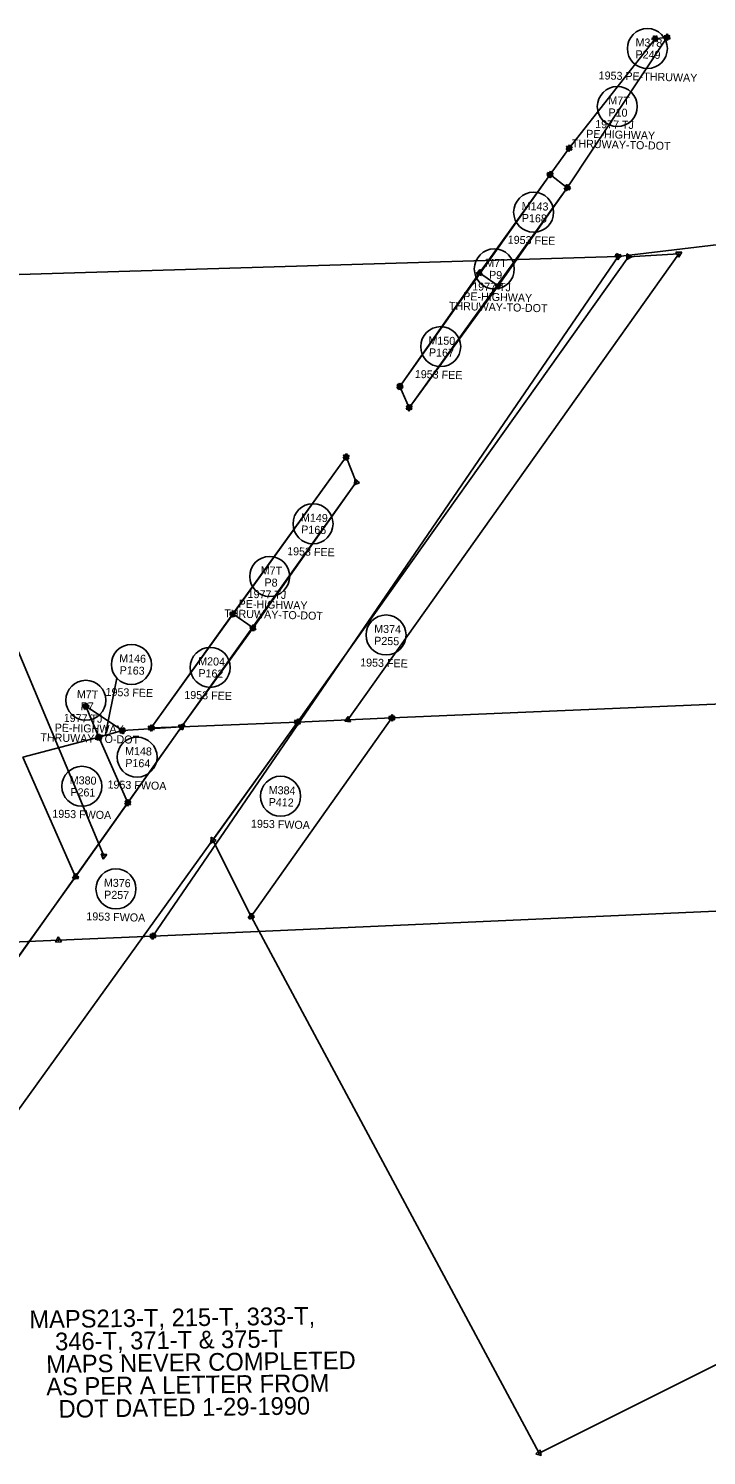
# Model space of a CAD drawing. Extents: x 325029 to 414988, y 1517527 to 1550420.
# Drawn here: x 360105 to 360549, y 1524410 to 1525346 of the extents above; entities that cross this region are included whole.
import ezdxf

# ---------------------------------------------------------------- set-up
doc = ezdxf.new("R2010")
doc.units = 0
for name, color, linetype in [('Level 56', 7, 'Continuous'), ('MEE', 7, 'Continuous'), ('MHB', 7, 'Continuous'), ('MHBWOA', 7, 'Continuous'), ('MRBL1', 7, 'Continuous'), ('MRBL2', 7, 'Continuous'), ('MRBL3', 7, 'Continuous'), ('NNSH_P_T', 7, 'Continuous'), ('S_C', 7, 'Continuous')]:
    doc.layers.add(name, color=color, linetype=linetype)

msp = doc.modelspace()

# ---------------------------------------------------------------- linework, layer by layer
at = {"layer": 'Level 56'}
for centre in [(360510.67, 1525333.37), (360490.95, 1525295.34), (360436.07, 1525226), (360410.26, 1525188.82), (360375.12, 1525137.86), (360291.35, 1525021.65), (360262.93, 1524987.07), (360339.26, 1524948.69), (360172.22, 1524929.34), (360223.9, 1524927.42), (360142.33, 1524905.83), (360175.95, 1524868.55), (360139.74, 1524849.41), (360270.07, 1524842.89), (360162.08, 1524782.11)]:
    msp.add_circle(centre, 13.12, dxfattribs=at)
at = {"layer": 'MEE'}
for p, q in [((360523.65, 1525340.76), (360458.11, 1525242.04)), ((360515.7, 1525339.83), (360459.32, 1525268.09)), ((360515.7, 1525339.83), (360523.65, 1525340.76)), ((360459.32, 1525268.09), (360446.84, 1525250.7)), ((360348.27, 1525111.73), (360446.84, 1525250.7)), ((360458.11, 1525242.04), (360354.48, 1525097.78)), ((360354.48, 1525097.78), (360348.27, 1525111.73)), ((360185.2, 1524887.67), (360313.03, 1525065.56)), ((360313.03, 1525065.56), (360319.76, 1525048.83)), ((360319.76, 1525048.83), (360205.18, 1524888.53)), ((360142.26, 1524901.89), (360166.29, 1524885.93)), ((360150.76, 1524881.6), (360142.26, 1524901.89))]:
    msp.add_line(p, q, dxfattribs=at)
for points in [[(360521.79, 1525339.62), (360523.59, 1525342.95)], [(360523.59, 1525342.95), (360525.57, 1525339.73)], [(360513.52, 1525339.86), (360516.82, 1525341.71)], [(360516.77, 1525337.93), (360513.52, 1525339.86)], [(360514.59, 1525337.95), (360514.64, 1525341.73)], [(360517.89, 1525339.8), (360514.59, 1525337.95)], [(360514.64, 1525341.73), (360517.89, 1525339.8)], [(360516.82, 1525341.71), (360516.77, 1525337.93)], [(360521.73, 1525341.8), (360525.5, 1525341.9)], [(360523.71, 1525338.58), (360521.73, 1525341.8)], [(360525.57, 1525339.73), (360521.79, 1525339.62)], [(360525.5, 1525341.9), (360523.71, 1525338.58)], [(360457.31, 1525267.24), (360459.58, 1525270.26)], [(360459.06, 1525265.92), (360457.58, 1525269.4)], [(360457.58, 1525269.4), (360461.33, 1525268.94)], [(360461.33, 1525268.94), (360459.06, 1525265.92)], [(360459.58, 1525270.26), (360461.06, 1525266.78)], [(360461.06, 1525266.78), (360457.31, 1525267.24)], [(360444.68, 1525250.99), (360448.17, 1525252.43)], [(360447.67, 1525248.69), (360444.68, 1525250.99)], [(360444.85, 1525249.81), (360447.06, 1525252.88)], [(360448.61, 1525249.43), (360444.85, 1525249.81)], [(360446.64, 1525248.53), (360445.07, 1525251.97)], [(360445.07, 1525251.97), (360448.83, 1525251.61)], [(360448.83, 1525251.61), (360446.64, 1525248.53)], [(360447.06, 1525252.88), (360448.61, 1525249.43)], [(360448.17, 1525252.43), (360447.67, 1525248.69)], [(360456.14, 1525241.11), (360458.28, 1525244.22)], [(360459.9, 1525240.8), (360456.14, 1525241.11)], [(360456.43, 1525240.65), (360457.75, 1525244.19)], [(360460.15, 1525241.27), (360456.43, 1525240.65)], [(360457.75, 1525244.19), (360460.15, 1525241.27)], [(360458.28, 1525244.22), (360459.9, 1525240.8)], [(360346.28, 1525110.84), (360348.5, 1525113.9)], [(360350.04, 1525110.44), (360346.28, 1525110.84)], [(360348.07, 1525109.55), (360346.49, 1525112.99)], [(360346.49, 1525112.99), (360350.25, 1525112.63)], [(360350.25, 1525112.63), (360348.07, 1525109.55)], [(360348.5, 1525113.9), (360350.04, 1525110.44)], [(360354.25, 1525095.61), (360352.71, 1525099.06)], [(360352.71, 1525099.06), (360356.47, 1525098.68)], [(360356.47, 1525098.68), (360354.25, 1525095.61)], [(360311.02, 1525064.7), (360313.29, 1525067.72)], [(360314.78, 1525064.25), (360311.02, 1525064.7)], [(360313.29, 1525067.72), (360314.78, 1525064.25)], [(360318.45, 1525047.09), (360318.9, 1525050.84)], [(360321.92, 1525048.58), (360318.45, 1525047.09)], [(360318.9, 1525050.84), (360321.92, 1525048.58)], [(360140.08, 1524902.02), (360143.47, 1524903.7)], [(360140.25, 1524901.05), (360142.54, 1524904.06)], [(360142.54, 1524904.06), (360144, 1524900.57)], [(360143.47, 1524903.7), (360143.23, 1524899.93)], [(360143.23, 1524899.93), (360140.08, 1524902.02)], [(360144, 1524900.57), (360140.25, 1524901.05)], [(360164.91, 1524884.24), (360165.51, 1524887.97)], [(360168.44, 1524885.59), (360164.91, 1524884.24)], [(360165.51, 1524887.97), (360168.44, 1524885.59)], [(360183.27, 1524888.68), (360187.04, 1524888.84)], [(360185.3, 1524885.49), (360183.27, 1524888.68)], [(360184.99, 1524885.49), (360183.43, 1524888.94)], [(360183.43, 1524888.94), (360187.19, 1524888.56)], [(360187.19, 1524888.56), (360184.99, 1524885.49)], [(360187.04, 1524888.84), (360185.3, 1524885.49)], [(360203, 1524888.59), (360206.32, 1524890.39)], [(360206.22, 1524886.62), (360203, 1524888.59)], [(360206.32, 1524890.39), (360206.22, 1524886.62)], [(360149.81, 1524879.64), (360149.54, 1524883.41)], [(360149.54, 1524883.41), (360152.94, 1524881.76)], [(360152.94, 1524881.76), (360149.81, 1524879.64)]]:
    msp.add_lwpolyline(points, dxfattribs=at)
for centre, radius in [((360515.7, 1525339.83), 0.227), ((360515.7, 1525339.83), 0.227), ((360523.65, 1525340.76), 0.227), ((360523.65, 1525340.76), 0.227), ((360459.32, 1525268.09), 0.227), ((360459.32, 1525268.09), 0.227), ((360446.85, 1525250.7), 1.09), ((360446.84, 1525250.7), 1.09), ((360446.84, 1525250.7), 0.227), ((360458.11, 1525242.04), 0.227), ((360458.11, 1525242.04), 0.227), ((360348.27, 1525111.73), 1.09), ((360348.27, 1525111.73), 1.09), ((360354.48, 1525097.78), 0.227), ((360313.03, 1525065.56), 0.227), ((360319.76, 1525048.83), 0.227), ((360142.27, 1524901.89), 1.09), ((360142.26, 1524901.89), 1.09), ((360166.29, 1524885.93), 0.227), ((360185.2, 1524887.67), 1.09), ((360185.2, 1524887.67), 1.09), ((360205.18, 1524888.53), 0.227), ((360150.76, 1524881.6), 0.227)]:
    msp.add_circle(centre, radius, dxfattribs=at)
at = {"layer": 'MHB'}
for p, q in [((360400.49, 1525186.25), (360446.84, 1525250.7)), ((360446.84, 1525250.7), (360458.11, 1525242.04)), ((360458.11, 1525242.04), (360412.87, 1525177.78)), ((360281.17, 1524891.53), (360498.27, 1525196.82)), ((360531.28, 1525198.68), (360314.14, 1524892.99)), ((360498.27, 1525196.82), (360531.28, 1525198.68)), ((360400.49, 1525186.25), (360348.27, 1525111.73)), ((360412.87, 1525177.78), (360400.49, 1525186.25)), ((360354.48, 1525097.78), (360412.87, 1525177.78)), ((360238.82, 1524962.45), (360313.03, 1525065.56)), ((360319.76, 1525048.83), (360252.02, 1524953.42)), ((360185.2, 1524887.67), (360238.82, 1524962.45)), ((360252.02, 1524953.42), (360238.82, 1524962.45)), ((360252.02, 1524953.42), (360205.18, 1524888.53)), ((360205.18, 1524888.53), (360185.2, 1524887.67))]:
    msp.add_line(p, q, dxfattribs=at)
for points in [[(360444.68, 1525250.99), (360448.17, 1525252.43)], [(360447.67, 1525248.69), (360444.68, 1525250.99)], [(360446.63, 1525248.53), (360445.08, 1525251.98)], [(360445.08, 1525251.98), (360448.83, 1525251.6)], [(360448.83, 1525251.6), (360446.63, 1525248.53)], [(360448.17, 1525252.43), (360447.67, 1525248.69)], [(360456.75, 1525243.74), (360460.26, 1525242.37)], [(360457.31, 1525240.01), (360456.75, 1525243.74)], [(360460.26, 1525242.37), (360457.31, 1525240.01)], [(360497.14, 1525194.95), (360497.22, 1525198.73)], [(360500.45, 1525196.77), (360497.14, 1525194.95)], [(360497.22, 1525198.73), (360500.45, 1525196.77)], [(360529.41, 1525199.81), (360533.18, 1525199.74)], [(360531.23, 1525196.5), (360529.41, 1525199.81)], [(360533.18, 1525199.74), (360531.23, 1525196.5)], [(360398.35, 1525185.88), (360401.25, 1525188.3)], [(360401.9, 1525184.58), (360398.35, 1525185.88)], [(360398.51, 1525185.33), (360400.68, 1525188.43)], [(360402.28, 1525185), (360398.51, 1525185.33)], [(360400.68, 1525188.43), (360402.28, 1525185)], [(360401.25, 1525188.3), (360401.9, 1525184.58)], [(360410.82, 1525178.52), (360414.54, 1525179.19)], [(360413.26, 1525175.64), (360410.82, 1525178.52)], [(360412.64, 1525175.61), (360411.11, 1525179.06)], [(360411.11, 1525179.06), (360414.87, 1525178.66)], [(360414.87, 1525178.66), (360412.64, 1525175.61)], [(360414.54, 1525179.19), (360413.26, 1525175.64)], [(360347, 1525109.95), (360347.36, 1525113.71)], [(360350.44, 1525111.52), (360347, 1525109.95)], [(360347.36, 1525113.71), (360350.44, 1525111.52)], [(360352.48, 1525096.89), (360354.71, 1525099.95)], [(360354.71, 1525099.95), (360356.24, 1525096.49)], [(360356.24, 1525096.49), (360352.48, 1525096.89)], [(360312.81, 1525063.39), (360311.26, 1525066.83)], [(360311.26, 1525066.83), (360315.02, 1525066.45)], [(360311.31, 1525066.9), (360315.05, 1525066.37)], [(360312.72, 1525063.4), (360311.31, 1525066.9)], [(360315.05, 1525066.37), (360312.72, 1525063.4)], [(360315.02, 1525066.45), (360312.81, 1525063.39)], [(360318.45, 1525047.09), (360318.9, 1525050.84)], [(360321.92, 1525048.58), (360318.45, 1525047.09)], [(360318.9, 1525050.84), (360321.92, 1525048.58)], [(360236.67, 1524962.08), (360239.57, 1524964.5)], [(360240.22, 1524960.78), (360236.67, 1524962.08)], [(360238.61, 1524960.28), (360237.05, 1524963.72)], [(360237.05, 1524963.72), (360240.81, 1524963.35)], [(360240.81, 1524963.35), (360238.61, 1524960.28)], [(360239.57, 1524964.5), (360240.22, 1524960.78)], [(360249.97, 1524954.16), (360253.69, 1524954.82)], [(360252.4, 1524951.27), (360249.97, 1524954.16)], [(360250.03, 1524952.52), (360252.24, 1524955.59)], [(360253.79, 1524952.14), (360250.03, 1524952.52)], [(360252.24, 1524955.59), (360253.79, 1524952.14)], [(360253.69, 1524954.82), (360252.4, 1524951.27)], [(360141.5, 1524899.84), (360140.88, 1524903.57)], [(360140.88, 1524903.57), (360144.42, 1524902.25)], [(360144.42, 1524902.25), (360141.5, 1524899.84)], [(360312.16, 1524892.09), (360314.34, 1524895.17)], [(360314.34, 1524895.17), (360315.92, 1524891.73)], [(360164.11, 1524886.07), (360167.5, 1524887.75)], [(360167.26, 1524883.97), (360164.11, 1524886.07)], [(360164.18, 1524886.48), (360167.82, 1524887.49)], [(360166.88, 1524883.83), (360164.18, 1524886.48)], [(360167.82, 1524887.49), (360166.88, 1524883.83)], [(360167.5, 1524887.75), (360167.26, 1524883.97)], [(360183.29, 1524886.63), (360185.27, 1524889.85)], [(360187.06, 1524886.52), (360183.29, 1524886.63)], [(360185.27, 1524889.85), (360187.06, 1524886.52)], [(360203, 1524888.6), (360206.33, 1524890.39)], [(360206.22, 1524886.61), (360203, 1524888.6)], [(360206.33, 1524890.39), (360206.22, 1524886.61)], [(360280.97, 1524889.36), (360279.4, 1524892.79)], [(360279.4, 1524892.79), (360283.16, 1524892.44)], [(360283.16, 1524892.44), (360280.97, 1524889.36)], [(360315.92, 1524891.73), (360312.16, 1524892.09)], [(360149.81, 1524879.64), (360149.54, 1524883.41)], [(360149.54, 1524883.41), (360152.94, 1524881.76)], [(360152.94, 1524881.76), (360149.81, 1524879.64)]]:
    msp.add_lwpolyline(points, dxfattribs=at)
for centre, radius in [((360446.85, 1525250.7), 1.09), ((360446.85, 1525250.71), 1.09), ((360458.11, 1525242.04), 0.227), ((360498.27, 1525196.82), 0.227), ((360531.28, 1525198.68), 0.227), ((360400.49, 1525186.25), 1.09), ((360400.49, 1525186.25), 0.227), ((360412.87, 1525177.78), 1.09), ((360412.87, 1525177.78), 0.227), ((360348.27, 1525111.73), 0.227), ((360354.48, 1525097.78), 0.227), ((360313.03, 1525065.56), 1.09), ((360313.03, 1525065.56), 1.09), ((360319.76, 1525048.83), 0.227), ((360238.82, 1524962.46), 1.09), ((360238.82, 1524962.45), 0.227), ((360252.02, 1524953.41), 1.09), ((360252.02, 1524953.42), 0.227), ((360142.26, 1524901.89), 0.227), ((360314.14, 1524892.99), 1.09), ((360166.29, 1524885.93), 1.09), ((360166.29, 1524885.93), 1.09), ((360185.2, 1524887.67), 0.227), ((360205.18, 1524888.53), 0.227), ((360281.18, 1524891.53), 1.09), ((360150.76, 1524881.6), 0.227)]:
    msp.add_circle(centre, radius, dxfattribs=at)
at = {"layer": 'MHBWOA'}
for p, q in [((360927.62, 1524919.37), (360343.11, 1524894.28)), ((360343.11, 1524894.28), (360250.8, 1524764.06)), ((360343.11, 1524894.28), (360281.17, 1524891.53)), ((360205.18, 1524888.53), (360045.08, 1524662.84)), ((360093.54, 1524630.95), (360281.17, 1524891.53)), ((360166.29, 1524885.93), (360150.76, 1524881.6)), ((360205.18, 1524888.53), (360166.29, 1524885.93)), ((360169.83, 1524838.63), (360205.18, 1524888.53)), ((360281.17, 1524891.53), (360205.18, 1524888.53)), ((360281.17, 1524891.53), (360225.56, 1524813.99)), ((360150.76, 1524881.6), (360101.02, 1524868.52)), ((360150.76, 1524881.6), (360169.83, 1524838.63)), ((360101.02, 1524868.52), (360135.53, 1524789.97)), ((360135.53, 1524789.97), (360169.83, 1524838.63)), ((360225.56, 1524813.99), (360250.8, 1524764.06)), ((360135.53, 1524789.97), (360090.29, 1524726.9)), ((360250.8, 1524764.06), (360439.59, 1524412.08)), ((360439.59, 1524412.08), (361119.17, 1524751.72))]:
    msp.add_line(p, q, dxfattribs=at)
for points in [[(360279.18, 1524890.63), (360281.39, 1524893.7)], [(360281.39, 1524893.7), (360282.94, 1524890.26)], [(360341.13, 1524893.37), (360343.31, 1524896.45)], [(360341.18, 1524895.29), (360344.95, 1524895.45)], [(360343.21, 1524892.1), (360341.18, 1524895.29)], [(360341.2, 1524893.24), (360343.17, 1524896.46)], [(360343.17, 1524896.46), (360344.98, 1524893.14)], [(360344.95, 1524895.45), (360343.21, 1524892.1)], [(360343.31, 1524896.45), (360344.89, 1524893.02)], [(360164.24, 1524886.69), (360167.97, 1524887.33)], [(360166.66, 1524883.78), (360164.24, 1524886.69)], [(360167.97, 1524887.33), (360166.66, 1524883.78)], [(360203, 1524888.59), (360206.32, 1524890.39)], [(360206.22, 1524886.62), (360203, 1524888.59)], [(360203.23, 1524889.5), (360207, 1524889.75)], [(360205.33, 1524886.36), (360203.23, 1524889.5)], [(360204.98, 1524886.36), (360203.41, 1524889.79)], [(360203.41, 1524889.79), (360207.17, 1524889.44)], [(360207.17, 1524889.44), (360204.98, 1524886.36)], [(360207, 1524889.75), (360205.33, 1524886.36)], [(360206.32, 1524890.39), (360206.22, 1524886.62)], [(360282.94, 1524890.26), (360279.18, 1524890.63)], [(360279.24, 1524892.54), (360283.01, 1524892.71)], [(360279.24, 1524892.55), (360283.02, 1524892.7)], [(360281.26, 1524889.35), (360279.24, 1524892.55)], [(360281.27, 1524889.36), (360279.24, 1524892.54)], [(360280.96, 1524889.36), (360279.41, 1524892.8)], [(360279.41, 1524892.8), (360283.17, 1524892.42)], [(360283.17, 1524892.42), (360280.96, 1524889.36)], [(360283.02, 1524892.7), (360281.26, 1524889.35)], [(360283.01, 1524892.71), (360281.27, 1524889.36)], [(360344.89, 1524893.02), (360341.13, 1524893.37)], [(360344.98, 1524893.14), (360341.2, 1524893.24)], [(360148.65, 1524882.17), (360152.31, 1524883.14)], [(360151.31, 1524879.49), (360148.65, 1524882.17)], [(360148.96, 1524880.35), (360150.58, 1524883.77)], [(360152.73, 1524880.67), (360148.96, 1524880.35)], [(360150.58, 1524883.77), (360152.73, 1524880.67)], [(360152.31, 1524883.14), (360151.31, 1524879.49)], [(360167.84, 1524837.73), (360170.05, 1524840.8)], [(360171.6, 1524837.35), (360167.84, 1524837.73)], [(360169.64, 1524836.45), (360168.05, 1524839.88)], [(360168.05, 1524839.88), (360171.81, 1524839.54)], [(360171.81, 1524839.54), (360169.64, 1524836.45)], [(360170.05, 1524840.8), (360171.6, 1524837.35)], [(360224.32, 1524812.19), (360224.61, 1524815.96)], [(360227.73, 1524813.82), (360224.32, 1524812.19)], [(360224.61, 1524815.96), (360227.73, 1524813.82)], [(360133.55, 1524789.07), (360135.75, 1524792.14)], [(360134.25, 1524788.21), (360134.64, 1524791.97)], [(360134.64, 1524791.97), (360137.7, 1524789.75)], [(360135.75, 1524792.14), (360137.31, 1524788.7)], [(360137.31, 1524788.7), (360133.55, 1524789.07)], [(360137.7, 1524789.75), (360134.25, 1524788.21)], [(360248.83, 1524763.11), (360250.96, 1524766.23)], [(360252.6, 1524762.83), (360248.83, 1524763.11)], [(360249.59, 1524762.24), (360249.82, 1524766.01)], [(360252.97, 1524763.92), (360249.59, 1524762.24)], [(360249.82, 1524766.01), (360252.97, 1524763.92)], [(360250.96, 1524766.23), (360252.6, 1524762.83)], [(360437.46, 1524411.61), (360440.25, 1524414.16)], [(360441.06, 1524410.47), (360437.46, 1524411.61)], [(360440.25, 1524414.16), (360441.06, 1524410.47)]]:
    msp.add_lwpolyline(points, dxfattribs=at)
for centre, radius in [((360343.11, 1524894.28), 1.09), ((360343.11, 1524894.28), 1.09), ((360343.11, 1524894.28), 0.227), ((360166.29, 1524885.93), 0.227), ((360205.18, 1524888.53), 1.09), ((360205.19, 1524888.53), 1.09), ((360205.18, 1524888.53), 0.227), ((360281.17, 1524891.53), 1.09), ((360281.18, 1524891.53), 1.09), ((360281.17, 1524891.53), 1.09), ((360281.17, 1524891.53), 1.09), ((360150.76, 1524881.6), 1.09), ((360150.76, 1524881.6), 0.227), ((360169.83, 1524838.63), 1.09), ((360169.83, 1524838.63), 0.227), ((360225.56, 1524813.99), 0.227), ((360135.53, 1524789.97), 0.227), ((360135.53, 1524789.97), 0.227), ((360250.8, 1524764.06), 0.227), ((360250.8, 1524764.06), 0.227), ((360439.59, 1524412.08), 0.227)]:
    msp.add_circle(centre, radius, dxfattribs=at)
at = {"layer": 'MRBL1'}
for p, q in [((360491.49, 1525197.03), (360752.09, 1525227.64)), ((360186.3, 1524751.19), (360491.49, 1525197.03))]:
    msp.add_line(p, q, dxfattribs=at)
for points in [[(360490.44, 1525195.12), (360490.36, 1525198.89)], [(360490.36, 1525198.89), (360493.67, 1525197.07)], [(360493.67, 1525197.07), (360490.44, 1525195.12)], [(360186.14, 1524749.01), (360184.51, 1524752.42)], [(360184.51, 1524752.42), (360188.27, 1524752.13)], [(360188.27, 1524752.13), (360186.14, 1524749.01)]]:
    msp.add_lwpolyline(points, dxfattribs=at)
for centre, radius in [((360491.49, 1525197.03), 0.227), ((360186.31, 1524751.19), 1.09)]:
    msp.add_circle(centre, radius, dxfattribs=at)
at = {"layer": 'MRBL2'}
for p, q in [((360491.49, 1525197.03), (359995.71, 1525182.03)), ((360186.3, 1524751.19), (360837.69, 1524780.1)), ((357681.26, 1524640), (360124.37, 1524748.44)), ((360124.37, 1524748.44), (360186.3, 1524751.19))]:
    msp.add_line(p, q, dxfattribs=at)
for points in [[(360489.57, 1525198.07), (360493.34, 1525198.18)], [(360491.55, 1525194.85), (360489.57, 1525198.07)], [(360493.34, 1525198.18), (360491.55, 1525194.85)], [(360184.47, 1524750.01), (360186.21, 1524753.36)], [(360186.21, 1524753.36), (360188.24, 1524750.18)], [(360122.53, 1524747.26), (360124.27, 1524750.61)], [(360126.3, 1524747.43), (360122.53, 1524747.26)], [(360124.27, 1524750.61), (360126.3, 1524747.43)], [(360188.24, 1524750.18), (360184.47, 1524750.01)]]:
    msp.add_lwpolyline(points, dxfattribs=at)
for centre, radius in [((360491.49, 1525197.03), 1.09), ((360124.37, 1524748.44), 0.227), ((360186.3, 1524751.19), 0.227)]:
    msp.add_circle(centre, radius, dxfattribs=at)
at = {"layer": 'MRBL3'}
msp.add_line((359995.71, 1525182.03), (360154.03, 1524803.87), dxfattribs=at)
for points in [[(360152.29, 1524805.19), (360156.04, 1524804.71)], [(360153.75, 1524801.71), (360152.29, 1524805.19)], [(360156.04, 1524804.71), (360153.75, 1524801.71)]]:
    msp.add_lwpolyline(points, dxfattribs=at)
msp.add_circle((360154.03, 1524803.87), 1.09, dxfattribs=at)
at = {"layer": 'S_C'}
msp.add_line((360155.19, 1524883.46), (360162.7, 1524920.31), dxfattribs=at)

# ---------------------------------------------------------------- texts
at = {"layer": 'Level 56'}
for s, height, p in [('M378', 5.249, (360502.83, 1525334.89)), ('P249', 5.249, (360502.81, 1525327.02)), ('1953 PE-THRUWAY', 5.2493, (360478.66, 1525313.2)), ('M7T', 5.249, (360485.01, 1525296.81)), ('P10', 5.249, (360485.09, 1525288.93)), ('PE-HIGHWAY', 5.249, (360470.48, 1525274.86)), ('1977 TJ', 5.249, (360476.41, 1525281.27)), ('THRUWAY-TO-DOT', 5.2493, (360461.09, 1525268.53)), ('M143', 5.249, (360428.16, 1525227.52)), ('P168', 5.249, (360428.28, 1525219.64)), ('1953 FEE', 5.249, (360419.04, 1525205.43)), ('M7T', 5.249, (360404.32, 1525190.29)), ('P9', 5.249, (360406.76, 1525182.35)), ('1977 TJ', 5.249, (360395.72, 1525174.75)), ('THRUWAY-TO-DOT', 5.2493, (360380.4, 1525162.01)), ('PE-HIGHWAY', 5.249, (360389.79, 1525168.34)), ('M150', 5.249, (360367.01, 1525139.39)), ('P167', 5.249, (360367.33, 1525131.5)), ('1953 FEE', 5.249, (360358.08, 1525117.29)), ('M149', 5.249, (360283.4, 1525023.18)), ('P165', 5.249, (360283.56, 1525015.3)), ('1953 FEE', 5.249, (360274.32, 1525001.08)), ('M7T', 5.249, (360256.99, 1524988.54)), ('1977 TJ', 5.249, (360248.39, 1524973)), ('P8', 5.249, (360259.45, 1524980.59)), ('PE-HIGHWAY', 5.249, (360242.46, 1524966.58)), ('THRUWAY-TO-DOT', 5.2493, (360233.07, 1524960.26)), ('M374', 5.249, (360331.42, 1524950.21)), ('P255', 5.249, (360331.43, 1524942.33)), ('M146', 5.249, (360164.17, 1524930.87)), ('M204', 5.249, (360215.97, 1524928.95)), ('1953 FEE', 5.249, (360322.22, 1524928.12)), ('P163', 5.249, (360164.45, 1524922.99)), ('P162', 5.249, (360216.11, 1524921.07)), ('M7T', 5.249, (360136.39, 1524907.3)), ('1953 FEE', 5.249, (360155.19, 1524908.77)), ('P7', 5.249, (360138.85, 1524899.36)), ('1953 FEE', 5.249, (360206.86, 1524906.85)), ('1977 TJ', 5.249, (360127.79, 1524891.76)), ('THRUWAY-TO-DOT', 5.2493, (360112.47, 1524879.02)), ('PE-HIGHWAY', 5.249, (360121.87, 1524885.35)), ('M148', 5.249, (360168.02, 1524870.07)), ('P164', 5.249, (360168.16, 1524862.19)), ('M380', 5.249, (360131.71, 1524850.93)), ('P261', 5.249, (360132.13, 1524843.05)), ('1953 FWOA', 5.249, (360156.49, 1524848.04)), ('M384', 5.249, (360262.22, 1524844.41)), ('P412', 5.249, (360262.22, 1524836.53)), ('1953 FWOA', 5.249, (360120.29, 1524828.9)), ('1953 FWOA', 5.249, (360250.61, 1524822.38)), ('M376', 5.249, (360154.11, 1524783.64)), ('P257', 5.249, (360154.25, 1524775.76)), ('1953 FWOA', 5.249, (360142.62, 1524761.6))]:
    msp.add_text(s, height=height, rotation=358.49067, dxfattribs=at).set_placement(p)
at = {"layer": 'NNSH_P_T'}
for s, p in [('MAPS213-T, 215-T, 333-T,', (360105.33, 1524493.9)), ('346-T, 371-T & 375-T', (360122.22, 1524479.38)), ('MAPS NEVER COMPLETED', (360116.42, 1524464.56)), ('AS PER A LETTER FROM', (360116.43, 1524449.83)), ('DOT DATED 1-29-1990', (360124.49, 1524435.19))]:
    msp.add_text(s, height=11.6264, rotation=0.74623, dxfattribs=at).set_placement(p)

doc.saveas('drawing.dxf')
